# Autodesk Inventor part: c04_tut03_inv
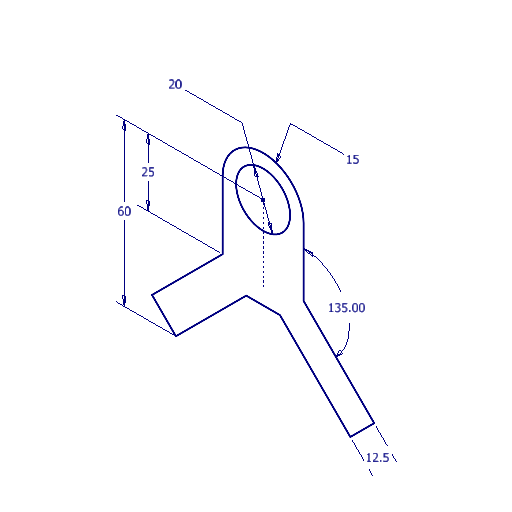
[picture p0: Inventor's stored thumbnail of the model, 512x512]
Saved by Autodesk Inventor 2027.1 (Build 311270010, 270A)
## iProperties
Created: 2017-04
Part Number: c04_tut03_inv
Material: Generic
Document SubType Name: Modeling
Designer: CADCIM 00
Density: 1 g/cm^3
Appearance: Default
Author: CADCIM 00
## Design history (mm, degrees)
sketch "Sketch1"
  geometry: L1 (-6.25, -33.928)-(6.25, -33.928); L2 (6.25, -33.928)-(32.322, -60); L3 (32.322, -60)-(41.161, -51.161); L4 (41.161, -51.161)-(15, -25); L5 (15, -25)-(15, 0); L6 (-15, 0)-(-15, -25); L7 (-15, -25)-(-41.161, -51.161); L8 (-41.161, -51.161)-(-32.322, -60); L9 (-32.322, -60)-(-6.25, -33.928); L10 (0, 0)-(0, -28.219); C1 r 10 at (0, 0); A1 r 15 centre (0, 0) between (15, 0) and (-15, 0); 1 further point
  constraints: 20 end point, 5 perpendicular, 2 centre point, 2 coincident, 2 point on circle, 2 symmetric about line, 2 tangent, 1 concentric, 1 equal length, 1 horizontal, 1 parallel, 1 point on line, 1 vertical, 2 other
  dimensions: "d0" = 15 radius of A1; "d1" = 135 deg angle of L7 L6; "d2" = 12.5 distance of L7.end L8.end; "d3" = 60 vertical distance of L2.end L10.start; "d4" = 25 vertical distance of L10.start L4.end; "d5" = 20 diameter of C1
